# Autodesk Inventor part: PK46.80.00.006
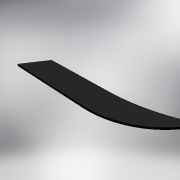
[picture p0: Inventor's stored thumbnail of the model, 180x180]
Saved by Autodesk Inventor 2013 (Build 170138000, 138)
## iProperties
Shininess: 64.0
Length Units: 11269
Angle Units: 11279
Time Units: 11290
Mass Units: 11283
Length Display Precision: 3
Angle Display Precision: 2
Compacted: True
Part Number: PK46.80.00.006
Document SubType Name: Modeling
Created: 2005-01
Material: Steel, Mild
Designer: SAlex
Manufacturer: Standard
Standards Organization: Custom
Density: 7.86 g/cm^3
Mass: 7427.61 g
Surface Area: 2063.9 cm^2
Volume: 944.989 cm^3
Density: 0.0
Volumn: 0.0
Area: 0.0
PropertySet Name: Model Information
Control State: 0
Master: False
Checked Out: False
Checked Out Date: 2008-10-15
Last Check In Date: 2008-10-15
Author: SAlex
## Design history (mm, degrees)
sketch "Sketch1"
  geometry: L1 (0, 0)-(456.881, 0); L2 (468.348, 140)-(85, 140); L3 (85, 140)-(0, 0); A1 r 410 centre (456.881, 410) between (456.881, 0) and (786.057, 165.577); A2 r 20 centre (770, 177.5) between (786.057, 165.577) and (762.643, 196.098); A3 r 800 centre (468.348, 940) between (468.348, 140) and (762.643, 196.098)
  constraints: 6 end point, 6 point on circle, 4 tangent, 3 centre point, 1 horizontal, 1 parallel, 1 other
  dimensions: "d0" = 770 horizontal distance of A2.centre L1.start; "d2" = 20 radius of A2; "d3" = 410 radius of A1; "d4" = 177.5 distance from line of A2.centre L1; "d5" = 800 radius of A3; "d6" = 85 horizontal distance of L2.end L1.start; "d7" = 140 distance between parallel lines of L2 L1
extrude "Extrusion1" new body sketch "Sketch1" distance "d8" = 10; taper "d9" = 0 deg
body "Solid1"
